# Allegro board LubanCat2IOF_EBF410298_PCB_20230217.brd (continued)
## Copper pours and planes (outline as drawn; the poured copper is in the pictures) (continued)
VCC5V0_USB on TOP: 11.91,76.02 11.99,75.84 12.17,75.76 15.16,75.76 15.34,75.84 15.42,76.02 15.42,78 15.34,78.18 15.16,78.25 12.17,78.25 11.99,78.18 11.91,78
VCC5V0_USB on TOP: 117.22,81.2 117.3,81.02 117.47,80.95 119.51,80.95 119.69,81.02 119.76,81.2 119.76,82.47 119.69,82.65 119.51,82.72 117.47,82.72 117.3,82.65 117.22,82.47
VCC5V0_USB on BOTTOM: 128.78,96.95 128.85,96.77 129.03,96.69 130.18,96.69 130.35,96.77 130.43,96.95 130.43,98.34 130.35,98.52 130.18,98.6 129.03,98.6 128.85,98.52 128.78,98.34
VCC5V0_USB on BOTTOM: 28.6,86 30.66,86 30.86,86.2 30.86,86.79 30.99,86.91 32.23,86.91 32.36,86.79 32.36,85.54 32.23,85.42 28.6,85.42
VCC5V0_USB on BOTTOM: 124.21,96.95 124.28,96.77 124.46,96.69 125.6,96.69 125.78,96.77 125.86,96.95 125.86,98.34 125.78,98.52 125.6,98.6 124.46,98.6 124.28,98.52 124.21,98.34
VCC5V0_USB on BOTTOM: 11.35,77.77 15.11,77.77 15.32,77.57 15.32,76.12 15.19,75.99 11.99,75.99 11.86,75.87 11.86,74.95 11.25,74.95 11.25,77.67
VCC5V0_USB on ART04: 46.48,87.4 47.4,88.31 47.4,96.95 47.9,97.46 54.36,97.46 55.22,98.32 107.85,98.32 108.36,97.81 121.67,97.81 122.17,98.32 125.02,98.32 125.32,98.01 128.73,98.01 128.93,98.22 130.1,98.22 130.35,97.96 130.35,94.56 130.05,94.26 118.52,94.26 118.01,93.75 118.01,84.1 118.26,83.84 119.48,83.84 119.68,83.64 119.68,82.22 119.48,82.01 116.38,82.01 116.2,82.19 116.2,92.15 115.93,92.43 97.59,92.43 96.93,93.09 96.93,96.19 96.22,96.9 56.18,96.9 55.07,95.78 50.65,95.78 49.89,95.02 49.89,83.28 49.17,82.57 17.73,82.57 16.71,81.56 16.71,76.42 16.31,76.02 9.25,76.02 8.79,76.48 8.79,86.64 9.55,87.4
VDD_3V3 on TOP: 95.02,21.61 95.1,21.43 95.28,21.36 97.94,21.36 98.12,21.43 98.2,21.61 98.2,21.79 98.12,21.97 97.94,22.04 95.28,22.04 95.1,21.97 95.02,21.79
VDD_3V3 on TOP: 142.37,64.69 142.44,64.51 142.62,64.44 144.15,64.44 144.32,64.51 144.4,64.69 144.4,65.96 144.32,66.14 144.15,66.21 142.62,66.21 142.44,66.14 142.37,65.96
VDD_3V3 on TOP: 2.77,31.21 8.79,31.21 9.27,30.73 9.27,17.12 9.47,16.91 10.74,16.91 11,16.66 11,14.83 11.18,14.65 12.83,14.65 13,14.83 13,17.9 12.83,18.08 11.35,18.08 11.23,18.21 11.23,33.37 11,33.6 6.86,33.6 6.86,32.79 6.68,32.61 2.77,32.61
VDD_3V3 on TOP: 145.85,41.5 142.77,41.5 142.54,41.73 142.54,43.35 143.76,43.35 143.76,42.46 143.94,42.29 145.85,42.29 145.97,42.16 145.97,41.63
VDD_3V3 on TOP: 142.32,12.24 142.39,12.06 142.57,11.98 143.71,11.98 143.89,12.06 143.97,12.24 143.97,14.5 143.89,14.68 143.71,14.75 142.57,14.75 142.39,14.68 142.32,14.5
VDD_3V3 on BOTTOM: 21.23,81.33 19.81,81.33 19.66,81.17 19.66,78.86 19.81,78.71 20.42,78.71 20.57,78.86 20.57,80.23 20.75,80.41 21.23,80.41
VDD_3V3 on PWR05: 2,5.5 0.94,5.94 0.5,7 0.5,98 0.94,99.06 2,99.5 4.52,99.5 4.52,96.39 7.39,96.39 7.39,99.5 17.88,99.5 17.88,97.58 19.38,97.58 19.38,99.5 156,99.5 157.06,99.06 157.5,98 157.5,7 157.06,5.94 156,5.5 ; 5 cut-outs
VDD_3V3_EDP_TP on TOP: 99.01,17.47 99.01,21.89 99.14,22.02 100.66,22.02 100.66,21.41 99.82,21.41 99.62,21.21 99.62,17.47 99.49,17.34 99.14,17.34
VDD_5V on TOP: 122.22,63.42 122.22,65.71 122,65.93 119.76,65.93 119.53,65.71 119.53,64.64 119.74,64.44 121.39,64.44 121.51,64.31 121.51,63.42
VDD_5V on TOP: 142.37,68.63 142.44,68.45 142.62,68.37 144.15,68.37 144.32,68.45 144.4,68.63 144.4,69.9 144.32,70.08 144.15,70.15 142.62,70.15 142.44,70.08 142.37,69.9
VDD_5V on TOP: 136.53,60.3 133.02,60.3 132.87,60.14 132.87,58.49 133.02,58.34 135.36,58.34 135.51,58.49 135.51,59.43 135.66,59.58 136.53,59.58
VDD_5V on TOP: 142.37,57.32 142.44,57.14 142.62,57.07 144.15,57.07 144.32,57.14 144.4,57.32 144.4,58.59 144.32,58.77 144.15,58.85 142.62,58.85 142.44,58.77 142.37,58.59
VDD_5V on TOP: 142.37,60.63 142.44,60.45 142.62,60.37 144.15,60.37 144.32,60.45 144.4,60.63 144.4,61.9 144.32,62.08 144.15,62.15 142.62,62.15 142.44,62.08 142.37,61.9
VDD_5V on TOP: 144.12,38.68 144.12,39.14 143.97,39.29 142.57,39.29 142.57,38.65 143.05,38.65 143.33,38.38 143.33,37.16 143.54,36.95 144.81,36.95 144.96,37.11 144.96,38.35 144.83,38.48 144.32,38.48
VDD_5V on TOP: 2.77,45.18 11.46,45.18 11.84,44.8 11.84,19.12 12.04,18.92 14.53,18.92 14.96,18.49 14.96,14.91 15.21,14.65 16.81,14.65 17.04,14.88 17.04,19.99 16.64,20.39 13.61,20.39 13.44,20.57 13.44,47.16 13.03,47.57 6.86,47.57 6.86,46.76 6.68,46.58 2.77,46.58
VDD_5V on BOTTOM: 118.95,63.12 119.02,62.94 119.2,62.86 121.97,62.86 122.15,62.94 122.22,63.12 122.22,65.71 122.15,65.89 121.97,65.96 119.76,65.96 119.58,65.78 119.58,64.23 119.38,64.03 119.02,64.03 118.95,63.95
VDD_5V on BOTTOM: 132.97,58.34 133.04,58.16 133.22,58.09 136.91,58.09 137.09,58.16 137.16,58.34 137.16,59.99 137.09,60.17 136.91,60.24 133.22,60.24 133.04,60.17 132.97,59.99
VDD_5V on BOTTOM: 28.04,79.68 28.04,81.78 28.24,81.99 29.46,81.99 29.67,81.78 29.67,80.64 29.26,80.23 29.26,79.5 28.22,79.5
VDD_5V on BOTTOM: 46.74,77.49 46.74,78.71 46.94,78.91 48.06,78.91 48.36,79.22 48.36,97.3 48.72,97.66 51.97,97.66 51.97,96.29 50.55,96.29 50.09,95.83 50.09,77.64 49.78,77.34 46.89,77.34
VDD_5V on ART04: 8.74,74.9 9.55,75.71 16.76,75.71 17.02,75.97 17.02,81.3 17.98,82.27 49.17,82.27 49.83,81.61 49.83,71.45 49.12,70.74 17.78,70.74 16.76,69.72 16.76,41.37 17.78,40.36 57.25,40.36 58.01,39.59 58.01,36.85 58.78,36.09 109.32,36.09 109.98,36.75 109.98,65.35 110.59,65.96 121.92,65.96 122.12,65.76 122.12,63.47 121.26,62.61 121.26,52.4 120.85,51.99 118.87,51.99 118.52,51.63 118.52,44.17 118.92,43.76 132.33,43.76 132.89,44.32 132.89,53.41 132.54,53.77 130.86,53.77 130.45,54.17 130.45,59.97 130.66,60.17 135.18,60.17 135.38,59.97 135.38,58.44 135.18,58.24 134.52,58.24 134.26,57.98 134.26,56.31 134.52,56.05 140.72,56.05 140.97,56.31 140.97,62.86 140.94,62.89 140.94,64.77 140.97,64.79 140.97,69.62 141.48,70.13 144.73,70.13 145.24,69.62 145.24,37.26 144.98,37 143.1,37 142.6,37.51 131.37,37.51 130.61,36.75 130.61,31.21 129.9,30.5 9.65,30.5 8.74,31.42
VDD_CAM0_5V on TOP: 147.17,57.4 147.24,57.22 147.42,57.15 150.32,57.15 150.5,57.22 150.57,57.4 150.57,57.73 150.5,57.91 150.32,57.98 147.42,57.98 147.24,57.91 147.17,57.73
VDD_CAM0_5V on BOTTOM: 148.06,51.35 148.06,55.22 149,56.16 149,57.63 149.15,57.78 150.37,57.78 150.52,57.63 150.52,55.32 150.04,54.83 150.04,51.35 149.81,51.13 148.29,51.13
VDD_CAM1_5V on TOP: 147.19,68.88 147.27,68.7 147.45,68.63 150.37,68.63 150.55,68.7 150.62,68.88 150.62,69.13 150.55,69.31 150.37,69.39 147.45,69.39 147.27,69.31 147.19,69.13
VDD_CAM1_5V on BOTTOM: 148.16,69.82 150.57,69.82 150.77,70.02 150.77,70.63 152.1,70.63 152.1,69.24 151.64,68.78 148.29,68.78 148.16,68.91
VDD_LCD0_5V on TOP: 150.88,65.58 150.88,63.8 151.13,63.55 151.89,63.55 152.15,63.8 152.15,65.58
VDD_LCD1_3V3 on TOP: 145.06,43.35 147.09,43.35 147.27,43.53 147.27,44.42 150.37,44.42 150.5,44.29 150.5,43.96 150.62,43.84 152.12,43.84 152.12,43.05 149.91,43.05 149.78,43.18 149.78,43.71 149.66,43.84 147.98,43.84 147.88,43.73 147.88,42.82 147.8,42.74 145.06,42.74
VDD_LCD1_5V on TOP: 150.83,42.85 150.83,40.43 150.7,40.31 150.7,39.92 150.83,39.8 151.87,39.8 152.12,40.05 152.12,42.85
HDMI_5V on BOTTOM: 54.18,97.68 54.18,95.27 54.38,95.07 60.15,95.07 60.35,95.27 60.35,96.36 60.1,96.62 55.58,96.62 55.4,96.8 55.4,97.68
HDMI_5V on ART04: 56.82,81.25 56.82,96.29 57.1,96.57 60.17,96.57 60.35,96.39 60.35,95.25 60.17,95.07 58.27,95.07 58.04,94.84 58.04,81.53 57.76,81.25
M2PCIE_3V3 on TOP: 139.24,83.31 139.24,86.28 138.66,86.86 138.66,87.3 138.81,87.45 140.13,87.45 140.31,87.27 140.31,85.95 140.61,85.64 141,85.64 141,83.33 140.79,83.13 139.42,83.13
M2PCIE_3V3 on TOP: 136.02,67.81 136.02,70.02 136.19,70.2 137.54,70.2 137.69,70.35 137.69,71.32 139.04,71.32 139.22,71.14 139.22,68.02 139.01,67.81
M2PCIE_3V3 on TOP: 153.75,85.37 153.75,83.79 155.07,83.79 155.07,85.37
M2PCIE_3V3 on BOTTOM: 136.27,68.63 136.35,68.45 136.53,68.37 139.06,68.37 139.24,68.45 139.32,68.63 139.32,69.77 139.24,69.95 139.06,70.02 136.53,70.02 136.35,69.95 136.27,69.77
M2PCIE_3V3 on BOTTOM: 135.31,84.71 142.04,84.71 142.04,84.07 141.07,84.07 140.94,83.94 140.94,77.97 140.82,77.85 139.14,77.85 139.14,82.85 138.91,83.08 135.51,83.08 135.31,83.28
M2PCIE_3V3 on BOTTOM: 153.82,86.1 153.9,85.92 154.08,85.85 154.31,85.85 154.48,85.92 154.56,86.1 154.56,88.03 154.48,88.21 154.31,88.29 154.08,88.29 153.9,88.21 153.82,88.03
M2PCIE_3V3 on BOTTOM: 151.76,85.77 151.84,85.59 152.02,85.52 152.27,85.52 152.45,85.59 152.53,85.77 152.53,87.93 152.45,88.11 152.27,88.18 152.02,88.18 151.84,88.11 151.76,87.93
M2PCIE_3V3 on ART03: 138.63,86.99 138.63,88.67 139.04,89.07 152.15,89.07 152.45,88.77 152.45,85.77 152.25,85.57 151.69,85.57 151.49,85.77 151.49,87.75 151.23,88.01 140.51,88.01 140.16,87.65 140.16,86.99 139.95,86.79 138.84,86.79
M2PCIE_3V3 on ART04: 136.45,68.7 136.45,86.84 137.01,87.4 142.19,87.4 142.75,86.84 142.75,70.89 142.39,70.53 141.12,70.53 140.46,69.87 140.46,68.7 140.11,68.35 136.8,68.35
MINIPCIE_3V3 on TOP: 130.4,61.64 130.4,64.72 130.66,64.97 133.2,64.97 133.43,64.74 133.43,61.69 133.2,61.46 130.58,61.46
MINIPCIE_3V3 on BOTTOM: 133.53,61.67 133.53,64.82 133.32,65.02 132.03,65.02 131.83,64.82 131.83,61.67 132,61.49 133.35,61.49
MINIPCIE_3V3 on ART04: 104.5,67.08 104.5,77.03 105.36,77.9 131.88,77.9 133.15,76.63 133.15,62 132.59,61.44 127.3,61.44 126.75,62 126.75,73.12 126.14,73.73 118.11,73.73 117.65,73.28 117.65,67.03 117.3,66.67 104.9,66.67
SATA_5V on TOP: 123.95,19.73 124.03,19.55 124.21,19.48 125.6,19.48 125.78,19.55 125.86,19.73 125.86,24.68 125.78,24.86 125.6,24.94 124.21,24.94 124.03,24.86 123.95,24.68
SATA_5V on BOTTOM: 123.11,24.3 123.11,18.56 122.83,18.28 120.32,18.28 120.04,18 120.04,14.93 120.19,14.78 122.78,14.78 122.94,14.93 122.94,16.53 123.47,17.06 125.45,17.06 125.65,17.27 125.65,23.97 125.32,24.3
SATA_12V on TOP: 134.54,14.19 136.8,14.19 137.03,14.42 137.03,17.98 136.78,18.23 135.2,18.23 135.2,16.28 134.54,15.62
SATA_12V on BOTTOM: 135.05,17.75 136.78,17.75 137.03,17.5 137.03,15.08 136.8,14.86 128.35,14.86 128.02,15.19 128.02,16.94 128.24,17.17 130.33,17.17 130.78,16.71 134.85,16.71 135.05,16.91
USB_OTG_VBUS on TOP: 26.09,90.57 26.29,90.57 26.49,90.78 26.49,94.03 25.91,94.03 25.91,90.75
USB_OTG_VBUS on TOP: 21.11,94.03 21.11,89.12 21.26,88.97 22.76,88.97 22.91,89.12 22.91,91.69 22.73,91.87 21.74,91.87 21.69,91.92 21.69,94.03
USB_OTG_VBUS on BOTTOM: 21.29,89.48 22.25,89.48 22.4,89.33 22.4,88.92 22.61,88.72 24.99,88.72 25.22,88.49 25.22,86.15 25.37,86 27.28,86 27.28,85.42 24.66,85.42 24.59,85.49 24.59,87.52 24.43,87.68 21.29,87.68 21.11,87.85 21.11,89.3
USB_OTG_VBUS on BOTTOM: 21.03,90.72 21.11,90.55 21.29,90.47 26.24,90.47 26.42,90.55 26.49,90.72 26.49,91.69 26.42,91.87 26.24,91.94 21.29,91.94 21.11,91.87 21.03,91.69
N28501 on TOP: 3.2,66.87 3.2,64.94 3.1,64.84 2.36,64.84 2.29,64.92 2.29,66.87
N28533 on TOP: 5.59,67.84 3.61,67.84 3.43,67.66 3.43,64.28 3.3,64.16 2.79,64.16 2.79,62.76 5.08,62.76 5.08,64.13 4.65,64.13 4.42,64.36 4.42,67.03 4.55,67.15 5.59,67.15
N15590150 on TOP: 71.98,41.19 70.89,41.19 70.89,43.25 69.82,44.32 69.82,45.54 69.7,45.67 69.06,45.67 69.01,45.72 69.01,46.4 69.09,46.48 70.51,46.48 70.69,46.3 70.69,44.73 71.98,43.43
N15605093 on TOP: 92.43,41.19 91.34,41.19 91.34,43.25 90.27,44.32 90.27,45.54 90.14,45.67 89.51,45.67 89.46,45.72 89.46,46.4 89.53,46.48 90.96,46.48 91.14,46.3 91.14,44.73 92.43,43.43
N17345181 on TOP: 5.59,39.9 3.61,39.9 3.43,39.72 3.43,36.34 3.3,36.22 2.79,36.22 2.79,34.82 5.08,34.82 5.08,36.19 4.65,36.19 4.42,36.42 4.42,39.09 4.55,39.21 5.59,39.21
N17345235 on TOP: 3.2,38.93 3.2,37 3.1,36.9 2.36,36.9 2.29,36.98 2.29,38.93
N17366990 on TOP: 3.2,52.9 3.2,50.97 3.1,50.87 2.36,50.87 2.29,50.95 2.29,52.9
N17366996 on TOP: 5.59,53.87 3.61,53.87 3.43,53.69 3.43,50.31 3.3,50.19 2.79,50.19 2.79,48.79 5.08,48.79 5.08,50.16 4.65,50.16 4.42,50.39 4.42,53.06 4.55,53.18 5.59,53.18
N17409816 on TOP: 122.45,64.31 122.45,62.38 122.61,62.23 126.62,62.23 126.77,62.07 126.77,61.64 128.19,61.64 128.19,63.93 126.77,63.93 126.77,63.19 126.64,63.06 123.32,63.06 123.16,63.22 123.16,64.31
N17410026 on TOP: 123.34,61.18 123.42,61.01 123.6,60.93 125.6,60.93 125.78,61.01 125.86,61.18 125.86,61.72 125.78,61.9 125.6,61.97 123.6,61.97 123.42,61.9 123.34,61.72
N17468430 on BOTTOM: 17.53,85.67 17.53,84.3 17.78,84.04 20.7,84.04 20.9,83.84 20.9,82.42 21.06,82.27 22.17,82.27 22.17,83.51 21.69,83.51 21.51,83.69 21.51,84.68 18.41,84.68 18.26,84.83 18.26,85.7 18.08,85.87 17.73,85.87
N17485853 on TOP: 137.92,61.67 138,61.49 138.18,61.41 138.79,61.41 138.97,61.49 139.04,61.67 139.04,63.27 138.97,63.45 138.79,63.52 138.18,63.52 138,63.45 137.92,63.27
N17485857 on TOP: 135.64,61.24 136.63,61.24 136.78,61.39 136.78,63.98 136.55,64.21 136.02,64.21 136.02,65.63 138.3,65.63 138.3,64.23 137.97,64.23 137.72,63.98 137.72,60.75 137.52,60.55 135.64,60.55
N17577092 on TOP: 118.08,22.81 118.08,21.89 119.96,21.89 120.07,21.99 120.07,22.7 119.96,22.81
N17577104 on TOP: 117.12,25.19 117.12,23.34 117.35,23.11 120.55,23.11 120.7,22.96 120.7,22.4 122.07,22.4 122.07,24.68 120.68,24.68 120.68,24.18 120.55,24.05 117.98,24.05 117.83,24.2 117.83,25.19
N17804594 on TOP: 4.55,76.27 7.04,76.27 7.14,76.17 7.14,75.46 7.04,75.36 4.55,75.36
N17804606 on TOP: 3.61,78.66 3.61,76.68 3.76,76.53 8.26,76.53 8.41,76.37 8.41,75.87 9.8,75.87 9.8,78.15 5.69,78.15 5.54,78 5.54,77.67 5.44,77.57 4.39,77.57 4.29,77.67 4.29,78.66

Small or netless copper shapes (teardrops, artwork), in the pictures only: 4 on BOTTOM, 16 on ART04

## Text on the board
Ref Des/Silkscreen Bottom: 2_L | 2_H | 1_L | 1_H | 2_A | 2_B | 1_A | 1_B | T1OUT | GND | R1IN | T2OUT | T1IN | R1OUT | T7_TX | T7_RX | R2IN | U7_TX | U7_RX | 5V | 12V | SIM Card | TF Card | CAM0 | CAM1 | T2IN | R2OUT | T9_TX | T9_RX | U9_TX | U9_RX | RX | TX | NC | VIN7 | SDA_M0 | VIN6 | SCL_M0 | RESET | VIN5 | VIN4 | TP_INT | 3V3 | VIN1 | 20230217 | EBF410298
User.Comments: CR_1_2 | CR_UNNAMED_13 | CR_UNNAMED_5 | CR_UNNAMED_9
Ref Des/Silkscreen Top: DEBUG | RESET | GND | 3V3 | POWER OUT | ON/OFF | 5V | RTC | RECOVERY | 12V | USB_OTG | FAN | CAN | SPK | EAR | MIC | RS485 | HDMI | RS232 | ETH0 | ETH1 | UART9 | UART7 | EDP_TP | SARADC | MINI PCIE | USB2.0 HOST | USB3.0/USB2.0 HOST | SATA_POWER | PWR | B | A | USR | M.2 PCIE3.0 | IR_REC | TX | RX | DC_12V | SATA | 30 | MIPI DSI TX0 | MIPI DSI TX1 | EDP
DIMENSION: 2 | MASKROM | A
User.7: 2 | MASKROM | A
User.8: 1 | C61 | C68 | C67 | C89 | C30 | C28 | C248 | R84 | R85 | C166 | C74 | C75 | C7 | C15 | C53 | C54 | C247 | C246 | C6 | C4 | C19 | C16 | C18 | C32 | C33 | C79 | C80 | R18 | C1 | C52 | D4 | R13 | C37 | R20 | C36 | C34 | C35 | D1 | C240 | C241 | C138 | R51 | R59 | C239 | Q1 | R17 | R14 | C228 | C227 | C229 | R77 | C234 | R76 | C233 | R75 | R74 | C226 | R73 | C225 | C232 | C129 | C175 | C130 | C230 | C231 | C176 | C178 | C177 | C114 | C119 | C123 | C122 | L11 | C115 | C111 | C136 | C124 | C121 | C133 | C100 | R41 | R68 | C146 | C167 | C82 | C66 | C197 | C221 | C64 | R71 | C72 | C70 | C69 | C151 | C65 | C71 | C73 | C77 | C76 | C140 | C141 | C92 | C78 | C139 | C104 | C103 | C126 | C94 | C91 | C93 | C172 | C144 | C145 | C117 | C107 | C118 | C116 | R29 | R28 | L12 | C220 | R55 | R54 | R53 | L10 | L15 | C219 | C106 | C187 | C218 | C191 | C148 | C142 | C152 | C149 | C153 | C143 | L20 | L17 | L21 | L18 | L19 | L16 | C189 | C217 | C216 | C212 | C208 | C209 | C210 | C200 | C223 | C211 | C174 | C199 | C192 | C204 | C205 | C201 | C99 | C109 | C55 | C58 | C165 | C101 | C23 | C22 | C21 | C20 | C83 | R35 | C84 | R34 | C132 | C131 | C134 | C112 | C113 | C163 | C135 | C125 | C170 | C102 | C108 | C120 | C98 | C164 | C137 | C81 | C162 | C105 | C110 | C168 | C169 | C173 | C147 | C86 | C150 | C88 | C85 | C171 | C90 | C87 | C222 | C188 | C182 | C190 | C183 | C196 | C206 | C193 | R70 | R69 | C207 | C224 | C198 | C213 | C214 | C181 | C184 | C195 | C179 | C186 | C194 | C180 | C185 | C215 | 20230201 | EBF410297
User.11: FIGURE | SIZE | 10.0 | 19.685 | 21.654 | 25.591 | 27.559 | 27.598 | 29.528 | 31.496 | 33.465 | 35.43 | 39.37 | 47.244 | 48.425 | 59.055 | 62.0 | 62.992 | 72.047 | 78.74 | 94.5 | 125.98 | 166.142 | 25.59 | 35.433 | 40.0 | 43.307 | 74.803 | 125.984 | 127.953 | 47.24x23.62 | 66.93x23.62 | 86.61x39.37 | 106.299x35.429 | DRILL CHART: TOP to BOTTOM | ALL UNITS ARE IN MILS | PLATED | NON-PLATED | QTY | 1799 | 2 | 19 | 30 | 18 | 7 | 9 | 4 | 15 | 8 | 20 | 14 | 10 | 1 | 3 | 5
